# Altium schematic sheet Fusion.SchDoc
size A2
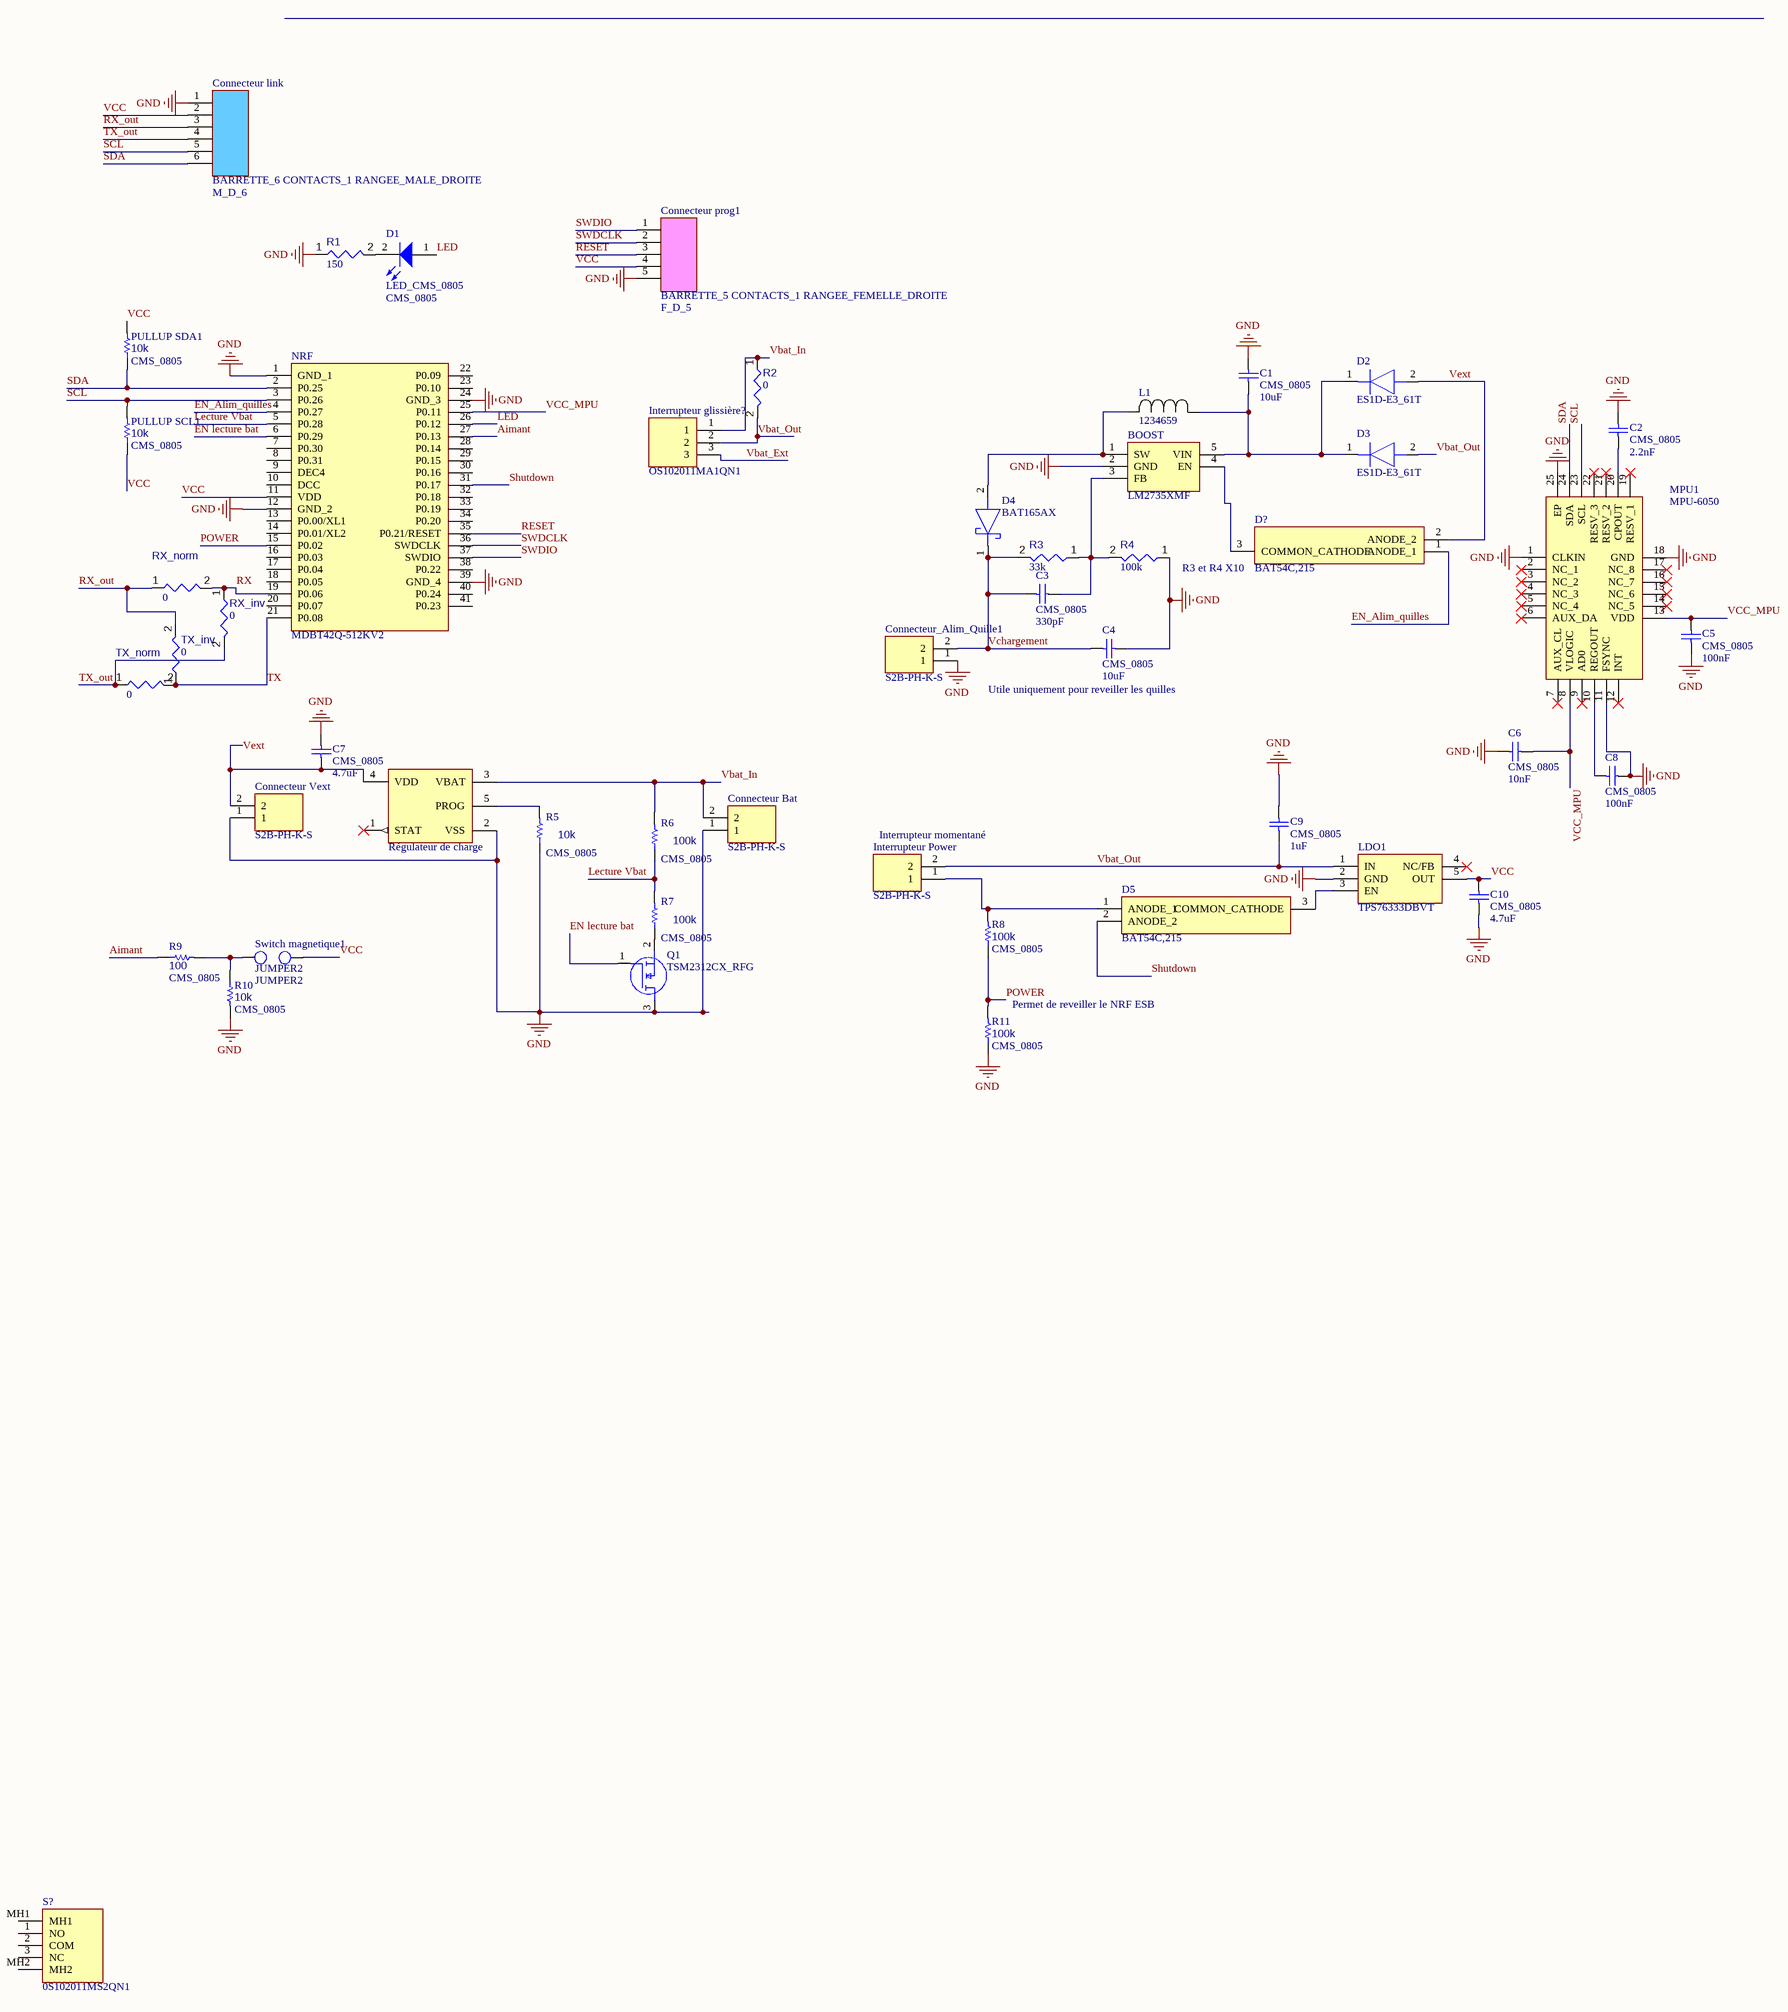
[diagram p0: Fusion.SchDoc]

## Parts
BOOST  LM2735XMF  [SOT95P285X110-5N]
C1  value 10uF  Type: CMS_0805  [CONDENSATEUR_CMS_0805]  (hidden comment: CONDENSATEUR_CMS_CER_0805)
C2  value 2.2nF  Type: CMS_0805  [CONDENSATEUR_CMS_0805]  (hidden comment: CONDENSATEUR_CMS_CER_0805)
C3  value 330pF  Type: CMS_0805  [CONDENSATEUR_CMS_0805]  (hidden comment: CONDENSATEUR_CMS_CER_0805)
C4  value 10uF  Type: CMS_0805  [CONDENSATEUR_CMS_0805]  (hidden comment: CONDENSATEUR_CMS_CER_0805)
C5  value 100nF  Type: CMS_0805  [CONDENSATEUR_CMS_0805]  (hidden comment: CONDENSATEUR_CMS_CER_0805)
C6  value 10nF  Type: CMS_0805  [CONDENSATEUR_CMS_0805]  (hidden comment: CONDENSATEUR_CMS_CER_0805)
C7  value 4.7uF  Type: CMS_0805  [CONDENSATEUR_CMS_0805]  (hidden comment: CONDENSATEUR_CMS_CER_0805)
C8  value 100nF  Type: CMS_0805  [CONDENSATEUR_CMS_0805]  (hidden comment: CONDENSATEUR_CMS_CER_0805)
C9  value 1uF  Type: CMS_0805  [CONDENSATEUR_CMS_0805]  (hidden comment: CONDENSATEUR_CMS_CER_0805)
C10  value 4.7uF  Type: CMS_0805  [CONDENSATEUR_CMS_0805]  (hidden comment: CONDENSATEUR_CMS_CER_0805)
Connecteur_Alim_Quille1  S2B-PH-K-S  [S2BPHKS]
Connecteur_Bat  S2B-PH-K-S  [S2BPHKS]
Connecteur_link  BARRETTE_6 CONTACTS_1 RANGEE_MALE_DROITE  Type: M_D_6  [BARRETTE_6_M_D]
Connecteur_prog1  BARRETTE_5 CONTACTS_1 RANGEE_FEMELLE_DROITE  Type: F_D_5  [BARRETTE_5_F_D]
Connecteur_Vext  S2B-PH-K-S  [S2BPHKS]
D1  LED_CMS_0805  Type: CMS_0805  [LED_CMS_0805]
D2  ES1D-E3_61T  [DIOM5127X229N]
D3  ES1D-E3_61T  [DIOM5127X229N]
D4  BAT165AX  [BAT165AX]
D5  BAT54C,215  [BAT54C215]
D?  BAT54C,215  [BAT54C215]
Interrupteur_glissière?  OS102011MA1QN1  [OS102011MA1QN1]
Interrupteur_Power  S2B-PH-K-S  [S2BPHKS]
L1  1234659  [IND_123_4659_RSP]
LDO1  TPS76333DBVT  [SOT95P280X145-5N]
MPU1  MPU-6050  [MPU6050]
NRF  MDBT42Q-512KV2  [MDBT42Q512KV2]
PULLUP_SCL1  value 10k  Type: CMS_0805  [RESISTANCE_CMS_0805]  (hidden comment: RESISTANCE_CMS_0805)
PULLUP_SDA1  value 10k  Type: CMS_0805  [RESISTANCE_CMS_0805]  (hidden comment: RESISTANCE_CMS_0805)
Q1  TSM2312CX_RFG  [SOT95P280X130-3N]
R1  value 150  [RESC0805(2012)_L]  (hidden comment: Resistor 1K +/-5% 0805 125 mW)
R2  value 0  [RESC1608X55X25ML10T15]  (hidden comment: Resistor 4k7 +/-1% 0603 100 mW)
R3  value 33k  [RESC2013X50X35ML15T15]  (hidden comment: Resistor 10k +/-1% 0805 125 mW)
R4  value 100k  [RESC2013X50X35ML15T15]  (hidden comment: Resistor 10k +/-1% 0805 125 mW)
R5  value 10k  Type: CMS_0805  [RESISTANCE_CMS_0805]  (hidden comment: RESISTANCE_CMS_0805)
R6  value 100k  Type: CMS_0805  [RESISTANCE_CMS_0805]  (hidden comment: RESISTANCE_CMS_0805)
R7  value 100k  Type: CMS_0805  [RESISTANCE_CMS_0805]  (hidden comment: RESISTANCE_CMS_0805)
R8  value 100k  Type: CMS_0805  [RESISTANCE_CMS_0805]  (hidden comment: RESISTANCE_CMS_0805)
R9  value 100  Type: CMS_0805  [RESISTANCE_CMS_0805]  (hidden comment: RESISTANCE_CMS_0805)
R10  value 10k  Type: CMS_0805  [RESISTANCE_CMS_0805]  (hidden comment: RESISTANCE_CMS_0805)
R11  value 100k  Type: CMS_0805  [RESISTANCE_CMS_0805]  (hidden comment: RESISTANCE_CMS_0805)
RX_inv  value 0  [RESC1608X55X25ML10T15]  (hidden comment: Resistor 4k7 +/-1% 0603 100 mW)
RX_norm  value 0  [RESC1608X55X25ML10T15]  (hidden comment: Resistor 4k7 +/-1% 0603 100 mW)
Régulateur_de_charge  MCP73831T-2DCI/OT  [SOT-23-OT5_N]  (value not drawn)
S?  0S102011MS2QN1  [0S102011MS2QN1]
Switch_magnetique1  JUMPER2  [BARRETTE_2_M_D]
TX_inv  value 0  [RESC1608X55X25ML10T15]  (hidden comment: Resistor 4k7 +/-1% 0603 100 mW)
TX_norm  value 0  [RESC1608X55X25ML10T15]  (hidden comment: Resistor 4k7 +/-1% 0603 100 mW)

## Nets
GND: BOOST.2(GND) C1.2 C2.2 C4.2 C5.1 C6.1 C7.2 C8.2 C9.2 C10.1 Connecteur_Alim_Quille1.1 Connecteur_Bat.1 Connecteur_link.1 Connecteur_prog1.5 Connecteur_Vext.1 LDO1.2(GND) MPU1.1(CLKIN) MPU1.11(FSYNC) MPU1.18(GND) MPU1.25(EP) NRF.1(GND_1) NRF.12(GND_2) NRF.24(GND_3) NRF.39(GND_4) Q1.3(D) R1.1 R4.1 R5.1 R10.2 R11.1 Régulateur_de_charge.2(VSS)
Aimant: NRF.27(P0.13) R9.1
EN lecture bat: NRF.6(P0.29) Q1.1(G)
EN_Alim_quilles: D?.1(ANODE_1) NRF.4(P0.27)
Lecture Vbat: NRF.5(P0.28) R6.1 R7.2
LED: D1.1 NRF.26(P0.12)
POWER: NRF.15(P0.02) R8.1 R11.2
RESET: Connecteur_prog1.3 NRF.35(P0.21/RESET)
RX: NRF.19(P0.06) RX_inv.1 RX_norm.2
RX_out: Connecteur_link.3 RX_norm.1 TX_inv.2
SCL: Connecteur_link.5 MPU1.23(SCL) NRF.3(P0.26) PULLUP_SCL1.2
SDA: Connecteur_link.6 MPU1.24(SDA) NRF.2(P0.25) PULLUP_SDA1.1
Shutdown: D5.2(ANODE_2) NRF.31(P0.17)
SWDCLK: Connecteur_prog1.2 NRF.36(SWDCLK)
SWDIO: Connecteur_prog1.1 NRF.37(SWDIO)
TX: NRF.21(P0.08) TX_inv.1 TX_norm.2
TX_out: Connecteur_link.4 RX_inv.2 TX_norm.1
Vbat_Ext: Interrupteur_glissière?.3
Vbat_In: Connecteur_Bat.2 Interrupteur_glissière?.1 R2.1 R6.2 Régulateur_de_charge.3(VBAT)
Vbat_Out: C9.1 D3.2(A) Interrupteur_glissière?.2 Interrupteur_Power.2 LDO1.1(IN) R2.2
VCC: C10.2 Connecteur_link.2 Connecteur_prog1.4 LDO1.5(OUT) NRF.11(VDD) PULLUP_SCL1.1 PULLUP_SDA1.2 Switch_magnetique1.2
VCC_MPU: C5.2 C6.2 MPU1.8(VLOGIC) MPU1.13(VDD) NRF.25(P0.11)
Vchargement: C3.1 C4.1 Connecteur_Alim_Quille1.2 D4.1(K) R3.2
Vext: C7.1 Connecteur_Vext.2 D2.2(A) D?.2(ANODE_2) Régulateur_de_charge.4(VDD)
NetBOOST_1: BOOST.1(SW) D4.2(A) L1.2
NetBOOST_3: BOOST.3(FB) C3.2 R3.1 R4.2
NetBOOST_4: BOOST.4(EN) D?.3(COMMON_CATHODE)
NetBOOST_5: BOOST.5(VIN) C1.1 D2.1(K) D3.1(K) L1.1
NetC2_1: C2.1 MPU1.20(CPOUT)
NetC8_1: C8.1 MPU1.10(REGOUT)
NetD1_2: D1.2 R1.2
NetD5_1: D5.1(ANODE_1) Interrupteur_Power.1 R8.2
NetD5_3: D5.3(COMMON_CATHODE) LDO1.3(EN)
NetQ1_2: Q1.2(S) R7.1
NetR5_2: R5.2 Régulateur_de_charge.5(PROG)
NetR9_2: R9.2 R10.1 Switch_magnetique1.1

Not connected (* = marked no-connect by the designer): LDO1 4(NC/FB)*; MPU1 2(NC_1)* 3(NC_2)* 4(NC_3)* 5(NC_4)* 6(AUX_DA)* 7(AUX_CL)* 9(AD0)* 12(INT)* 14(NC_5)* 15(NC_6)* 16(NC_7)* 17(NC_8)* 19(RESV_1)* 21(RESV_2)* 22(RESV_3)*; NRF 7(P0.30) 8(P0.31) 9(DEC4) 10(DCC) 13(P0.00/XL1) 14(P0.01/XL2) 16(P0.03) 17(P0.04) 18(P0.05) 20(P0.07) 22(P0.09) 23(P0.10) 28(P0.14) 29(P0.15) 30(P0.16) 32(P0.18) 33(P0.19) 34(P0.20) 38(P0.22) 40(P0.24) 41(P0.23); Régulateur_de_charge 1(STAT)*; S? 1(NO) 2(COM) 3(NC) MH1 MH2

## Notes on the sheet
- (near D?) R3 et R4 X10
- (near C4) Utile uniquement pour reveiller les quilles
- (near Interrupteur_Power) Interrupteur momentané
- (near R11) Permet de reveiller le NRF ESB

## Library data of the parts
BOOST = LM2735XMF: Integrated Circuit; Manufacturer_Name: Texas Instruments
C1-C10 = CMP-038-0003-1: CONDENSATEUR CMS CERAMIQUE 0805
Connecteur_Alim_Quille1 Connecteur_Bat Connecteur_Vext Interrupteur_Power = S2B-PH-K-S: Connector; Manufacturer_Name: JST (JAPAN SOLDERLESS TERMINALS)
Connecteur_link = CMP-039-0125-1: BARRETTE 6 CONTACTS 1 RANGEE MALE DROITE
Connecteur_prog1 = CMP-039-0118-1: BARRETTE 5 CONTACTS 1 RANGEE FEMELLE DROITE
D1 = CMP-024-0003-1: LED CMS 0805
D2 D3 = ES1D-E3_61T: Diode; Manufacturer_Name: Vishay; Manufacturer_Part_Number: ES1D-E3/61T
D4 = BAT165AX: Schottky Diode; Manufacturer_Name: Nexperia
D5 D? = BAT54C,215: Schottky Diode; Manufacturer_Name: Nexperia
Interrupteur_glissière? = OS102011MA1QN1: Switch; Manufacturer_Name: C & K COMPONENTS
L1 = 1234659: No Description Available; Mfr_Name: RS Pro; Type: DEV
LDO1 = TPS76333DBVT: Integrated Circuit; Manufacturer_Name: Texas Instruments
MPU1 = MPU-6050: Integrated Circuit; Manufacturer_Name: TDK
NRF = MDBT42Q-512KV2: Integrated Circuit; Manufacturer_Name: Raytac
PULLUP_SCL1 PULLUP_SDA1 R5-R11 = CMP-037-0001-1: RESISTANCE CMS 0805
Q1 = TSM2312CX_RFG: MOSFET (N-Channel); Manufacturer_Name: Taiwan Semiconductor; Manufacturer_Part_Number: TSM2312CX RFG
R1 = CMP-009-00118-3: Chip Resistor, 1 kOhms, +/-5%, 125 mW, -55 to 155 degC, 0805; Tolerance: 5%; Power: 125mW
R2 RX_inv RX_norm TX_inv TX_norm = CMP-009-00031-5: Chip Resistor, 4.7 KOhm, +/- 1%, 0.1 W, -55 to 155 degC, 0603 (1608 Metric); Power: 100mW
R3 R4 = CMP-009-00018-5: Chip Resistor, 10 KOhm, +/- 1%, 125 mW, -55 to 155 degC, 0805 (2012 Metric); Power: 125mW; Voltage Rating: 150V
Régulateur_de_charge = CMP-045-0000-1: Miniature Single-Cell, Fully Integrated Li-Ion, Li-Polymer Charge Management Controller, 4.2V, 5-Pin SOT-23, Industrial Temperature, Tape and Reel; Manufacturer: Microchip
S? = 0S102011MS2QN1: Switch; Manufacturer_Name: C & K COMPONENTS
Switch_magnetique1 = CMP-039-0004-1: BARRETTE 2 CONTACTS 1 RANGEE MALE DROITE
